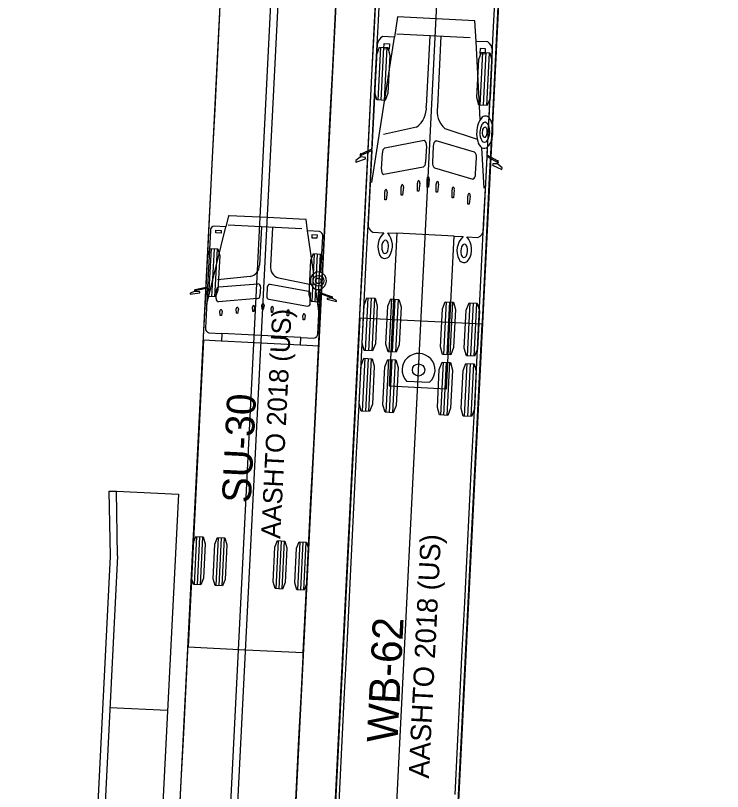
# Model space of a CAD drawing. Extents: x 260275 to 261282, y 610916 to 614143.
# Drawn here: x 261035.2 to 261084.3, y 612189.7 to 612243.5 of the extents above; entities that cross this region are included whole.
import ezdxf

# ---------------------------------------------------------------- set-up
doc = ezdxf.new("R2010")
doc.units = 0
for name, color, linetype in [('GE_X_Alignment', 7, 'Continuous'), ('PV_P_Curb', 7, 'Continuous'), ('PV_P_EOP', 7, 'Continuous'), ('PV_P_Joint', 7, 'Continuous'), ('TopoDOT_Transients', 7, 'Continuous')]:
    doc.layers.add(name, color=color, linetype=linetype)

msp = doc.modelspace()

# ---------------------------------------------------------------- linework, layer by layer
at = {"layer": 'GE_X_Alignment'}
msp.add_line((260986.249, 610915.954), (261148.276, 614142.838), dxfattribs=at)
at = {"layer": 'PV_P_Curb'}
for p, q in [((261041.738, 612210.53), (261042.238, 612210.54)), ((261041.822, 612206.045), (261041.738, 612210.53)), ((261041.82, 612206.041), (261037.345, 612116.921))]:
    msp.add_line(p, q, dxfattribs=at)
at = {"layer": 'PV_P_EOP'}
for p, q in [((261042.238, 612210.54), (261046.541, 612210.324)), ((261042.321, 612206.054), (261042.238, 612210.54)), ((261046.541, 612210.324), (261045.432, 612188.236)), ((261042.321, 612206.054), (261037.849, 612116.977))]:
    msp.add_line(p, q, dxfattribs=at)
at = {"layer": 'PV_P_Joint'}
msp.add_line((261041.794, 612195.543), (261045.789, 612195.343), dxfattribs=at)
at = {"layer": 'TopoDOT_Transients'}
for p, q in [((261059.045, 612136.423), (261081.046, 612574.591)), ((261048.059, 612136.974), (261068.197, 612538.052)), ((261067.093, 612243.166), (261061.729, 612243.435)), ((261066.768, 612241.979), (261061.669, 612242.235)), ((261063.969, 612242.12), (261063.724, 612237.234)), ((261059.937, 612231.949), (261061.508, 612242.018)), ((261064.734, 612242.081), (261064.488, 612237.196)), ((261067.467, 612236.32), (261067.172, 612241.733)), ((261060.537, 612241.326), (261060.353, 612237.663)), ((261060.766, 612241.314), (261060.582, 612237.652)), ((261060.778, 612241.218), (261060.796, 612241.573)), ((261061.156, 612241.199), (261060.778, 612241.218)), ((261060.796, 612241.573), (261061.174, 612241.554)), ((261060.994, 612241.303), (261060.811, 612237.641)), ((261061.174, 612241.554), (261061.156, 612241.199)), ((261067.458, 612241.239), (261067.44, 612240.883)), ((261067.836, 612241.22), (261067.458, 612241.239)), ((261067.818, 612240.864), (261067.836, 612241.22)), ((261068.071, 612236.423), (261068.307, 612241.118)), ((261067.611, 612240.97), (261067.427, 612237.308)), ((261067.44, 612240.883), (261067.818, 612240.864)), ((261067.84, 612240.959), (261067.656, 612237.297)), ((261068.069, 612240.947), (261067.885, 612237.285)), ((261063.051, 612235.787), (261060.759, 612235.268)), ((261065.012, 612235.688), (261067.253, 612234.939)), ((261060.845, 612234.359), (261063.568, 612234.868)), ((261067.064, 612234.047), (261064.406, 612234.826)), ((261063.731, 612234.489), (261063.674, 612233.36)), ((261064.206, 612234.465), (261064.149, 612233.336)), ((261067.727, 612231.558), (261067.574, 612234.358)), ((261059.164, 612233.717), (261059.143, 612233.702)), ((261059.19, 612233.715), (261059.164, 612233.717)), ((261060.618, 612232.868), (261060.675, 612233.997)), ((261067.141, 612232.54), (261067.197, 612233.669)), ((261063.504, 612232.997), (261060.781, 612232.489)), ((261068.646, 612233.24), (261068.672, 612233.24)), ((261068.672, 612233.24), (261068.692, 612233.222)), ((261064.282, 612232.958), (261066.941, 612232.179)), ((261063.784, 612231.619), (261063.775, 612232.17)), ((261063.929, 612232.162), (261063.866, 612231.615)), ((261061.988, 612231.065), (261061.98, 612231.641)), ((261062.134, 612231.634), (261062.07, 612231.061)), ((261063.121, 612231.343), (261063.112, 612231.894)), ((261063.267, 612231.886), (261063.203, 612231.339)), ((261063.866, 612231.615), (261063.784, 612231.619)), ((261064.416, 612231.278), (261064.407, 612231.829)), ((261064.561, 612231.821), (261064.498, 612231.274)), ((261065.515, 612230.888), (261065.506, 612231.439)), ((261065.66, 612231.431), (261065.597, 612230.884)), ((261060.853, 612230.736), (261060.845, 612231.287)), ((261060.999, 612231.279), (261060.935, 612230.732)), ((261062.07, 612231.061), (261061.988, 612231.065)), ((261063.203, 612231.339), (261063.121, 612231.343)), ((261064.498, 612231.274), (261064.416, 612231.278)), ((261065.597, 612230.884), (261065.515, 612230.888)), ((261066.611, 612230.447), (261066.603, 612230.998)), ((261066.757, 612230.99), (261066.693, 612230.443)), ((261060.935, 612230.732), (261060.853, 612230.736)), ((261066.693, 612230.443), (261066.611, 612230.447)), ((261048.494, 612223.403), (261049.834, 612228.871)), ((261055.089, 612228.73), (261049.99, 612228.986)), ((261052.29, 612228.871), (261052.156, 612226.206)), ((261053.054, 612228.832), (261052.921, 612226.167)), ((261049.123, 612228.45), (261049.133, 612228.644)), ((261049.501, 612228.431), (261049.123, 612228.45)), ((261049.133, 612228.644), (261049.511, 612228.625)), ((261049.511, 612228.625), (261049.501, 612228.431)), ((261055.916, 612225.621), (261055.498, 612228.586)), ((261055.795, 612228.31), (261055.785, 612228.116)), ((261056.173, 612228.291), (261055.795, 612228.31)), ((261056.163, 612228.097), (261056.173, 612228.291)), ((261056.419, 612225.711), (261056.546, 612228.23)), ((261060.014, 612228.502), (261060.788, 612228.463)), ((261065.644, 612228.22), (261061.675, 612228.419)), ((261066.53, 612228.175), (261067.305, 612228.136)), ((261055.785, 612228.116), (261056.163, 612228.097)), ((261048.801, 612227.366), (261048.634, 612224.036)), ((261049.009, 612227.355), (261048.842, 612224.026)), ((261049.217, 612227.345), (261049.05, 612224.015)), ((261055.959, 612227.006), (261055.791, 612223.677)), ((261056.167, 612226.996), (261056, 612223.667)), ((261056.375, 612226.985), (261056.208, 612223.656)), ((261051.518, 612225.43), (261049.239, 612225.199)), ((261049.346, 612224.7), (261052.054, 612224.916)), ((261053.478, 612225.331), (261055.734, 612224.871)), ((261049.153, 612223.89), (261049.184, 612224.506)), ((261052.226, 612224.705), (261052.195, 612224.089)), ((261052.701, 612224.681), (261052.67, 612224.065)), ((261055.566, 612224.387), (261052.892, 612224.874)), ((261056.284, 612223.012), (261056.067, 612224.546)), ((261052.033, 612223.895), (261049.325, 612223.679)), ((261052.811, 612223.856), (261055.484, 612223.369)), ((261055.676, 612223.562), (261055.707, 612224.178)), ((261059.664, 612223.947), (261059.48, 612220.285)), ((261059.893, 612223.936), (261059.709, 612220.274)), ((261060.122, 612223.924), (261059.938, 612220.262)), ((261061.312, 612223.865), (261061.128, 612220.203)), ((261061.541, 612223.853), (261061.357, 612220.191)), ((261061.77, 612223.842), (261061.586, 612220.18)), ((261051.688, 612222.999), (261051.667, 612223.301)), ((261051.821, 612223.293), (261051.77, 612222.995)), ((261052.344, 612223.135), (261052.323, 612223.436)), ((261052.477, 612223.428), (261052.426, 612223.131)), ((261065.091, 612223.675), (261064.907, 612220.013)), ((261065.319, 612223.663), (261065.136, 612220.001)), ((261065.548, 612223.652), (261065.364, 612219.99)), ((261066.739, 612223.592), (261066.555, 612219.93)), ((261066.967, 612223.581), (261066.784, 612219.919)), ((261067.196, 612223.569), (261067.012, 612219.907)), ((261049.437, 612222.719), (261049.416, 612223.02)), ((261049.57, 612223.013), (261049.519, 612222.715)), ((261050.563, 612222.873), (261050.542, 612223.188)), ((261050.645, 612222.869), (261050.563, 612222.873)), ((261050.696, 612223.181), (261050.645, 612222.869)), ((261051.77, 612222.995), (261051.688, 612222.999)), ((261052.426, 612223.131), (261052.344, 612223.135)), ((261052.983, 612222.934), (261052.962, 612223.236)), ((261053.065, 612222.93), (261052.983, 612222.934)), ((261053.116, 612223.228), (261053.065, 612222.93)), ((261054.089, 612222.696), (261054.068, 612222.997)), ((261054.223, 612222.99), (261054.172, 612222.692)), ((261049.519, 612222.715), (261049.437, 612222.719)), ((261054.172, 612222.692), (261054.089, 612222.696)), ((261055.195, 612222.43), (261055.174, 612222.731)), ((261055.277, 612222.426), (261055.195, 612222.43)), ((261055.328, 612222.724), (261055.277, 612222.426)), ((261055.037, 612221.196), (261049.552, 612221.472)), ((261055.01, 612220.666), (261049.525, 612220.941)), ((261059.453, 612219.753), (261059.27, 612216.091)), ((261059.682, 612219.741), (261059.498, 612216.079)), ((261059.911, 612219.73), (261059.727, 612216.068)), ((261061.101, 612219.67), (261060.918, 612216.008)), ((261061.33, 612219.658), (261061.146, 612215.996)), ((261061.559, 612219.647), (261061.375, 612215.985)), ((261064.88, 612219.48), (261064.696, 612215.818)), ((261065.109, 612219.469), (261064.925, 612215.807)), ((261065.338, 612219.457), (261065.154, 612215.795)), ((261066.528, 612219.398), (261066.344, 612215.735)), ((261066.757, 612219.386), (261066.573, 612215.724)), ((261066.986, 612219.375), (261066.802, 612215.712)), ((261062.341, 612218.176), (261063.955, 612218.095)), ((261047.798, 612207.391), (261047.631, 612204.062)), ((261048.006, 612207.38), (261047.839, 612204.051)), ((261048.214, 612207.37), (261048.047, 612204.041)), ((261049.296, 612207.315), (261049.129, 612203.986)), ((261049.504, 612207.305), (261049.337, 612203.976)), ((261049.712, 612207.295), (261049.545, 612203.965)), ((261053.458, 612207.106), (261053.29, 612203.777)), ((261053.666, 612207.096), (261053.498, 612203.767)), ((261053.874, 612207.086), (261053.707, 612203.756)), ((261054.956, 612207.031), (261054.789, 612203.702)), ((261055.164, 612207.021), (261054.997, 612203.692)), ((261055.372, 612207.01), (261055.205, 612203.681))]:
    msp.add_line(p, q, dxfattribs=at)
for points in [[(261051.548, 612071.863), (261074.206, 612523.277)], [(261082.631, 612521.243), (261060.03, 612071.291)], [(261042.767, 612111.356), (261063.016, 612514.614)], [(261070.923, 612512.551), (261050.75, 612110.806), (261042.76, 612111.207), (261042.767, 612111.356), (261042.767, 612111.356)], [(261054.56, 612186.696), (261054.728, 612190.025), (261054.895, 612193.353), (261055.062, 612196.681), (261055.229, 612200.01), (261055.396, 612203.338), (261055.563, 612206.667), (261055.73, 612209.995), (261055.897, 612213.324), (261056.065, 612216.652), (261056.232, 612219.981), (261056.399, 612223.309), (261056.566, 612226.637), (261056.733, 612229.966), (261056.9, 612233.294), (261057.067, 612236.623), (261057.234, 612239.951), (261057.402, 612243.28), (261057.569, 612246.608)], [(261054.561, 612186.7), (261054.728, 612190.029), (261054.895, 612193.357), (261055.062, 612196.686), (261055.229, 612200.014), (261055.396, 612203.342), (261055.563, 612206.671), (261055.73, 612209.999), (261055.898, 612213.328), (261056.065, 612216.656), (261056.232, 612219.985), (261056.399, 612223.313), (261056.566, 612226.642), (261056.733, 612229.97), (261056.9, 612233.298), (261057.068, 612236.627), (261057.235, 612239.955), (261057.402, 612243.284), (261057.569, 612246.612)], [(261057.558, 612186.566), (261057.725, 612189.896), (261057.892, 612193.225), (261058.059, 612196.555), (261058.226, 612199.884), (261058.394, 612203.214), (261058.561, 612206.544), (261058.728, 612209.873), (261058.895, 612213.203), (261059.062, 612216.532), (261059.229, 612219.862), (261059.397, 612223.191), (261059.564, 612226.521), (261059.731, 612229.85), (261059.898, 612233.18), (261060.065, 612236.509), (261060.233, 612239.839), (261060.4, 612243.169), (261060.567, 612246.498)], [(261057.45, 612189.416), (261057.618, 612192.746), (261057.785, 612196.075), (261057.952, 612199.405), (261058.119, 612202.734), (261058.286, 612206.064), (261058.454, 612209.394), (261058.621, 612212.723), (261058.788, 612216.053), (261058.955, 612219.382), (261059.122, 612222.712), (261059.289, 612226.041), (261059.457, 612229.371), (261059.624, 612232.7), (261059.791, 612236.03), (261059.958, 612239.359), (261060.125, 612242.689), (261060.293, 612246.019)], [(261065.715, 612189.495), (261065.882, 612192.824), (261066.049, 612196.154), (261066.216, 612199.483), (261066.384, 612202.813), (261066.551, 612206.142), (261066.718, 612209.472), (261066.885, 612212.801), (261067.052, 612216.131), (261067.219, 612219.461), (261067.387, 612222.79), (261067.554, 612226.12), (261067.721, 612229.449), (261067.888, 612232.779), (261068.055, 612236.108), (261068.223, 612239.438), (261068.39, 612242.767), (261068.557, 612246.097)], [(261065.94, 612188.99), (261066.107, 612192.32), (261066.274, 612195.649), (261066.441, 612198.979), (261066.608, 612202.308), (261066.776, 612205.638), (261066.943, 612208.967), (261067.11, 612212.297), (261067.277, 612215.626), (261067.444, 612218.956), (261067.612, 612222.285), (261067.779, 612225.615), (261067.946, 612228.945), (261068.113, 612232.274), (261068.28, 612235.604), (261068.447, 612238.933), (261068.615, 612242.263), (261068.782, 612245.592)], [(261046.57, 612187.097), (261046.738, 612190.426), (261046.905, 612193.754), (261047.072, 612197.083), (261047.239, 612200.411), (261047.406, 612203.739), (261047.573, 612207.068), (261047.74, 612210.396), (261047.907, 612213.725), (261048.075, 612217.053), (261048.242, 612220.382), (261048.409, 612223.71), (261048.576, 612227.039), (261048.743, 612230.367), (261048.91, 612233.695), (261049.077, 612237.024), (261049.244, 612240.352), (261049.412, 612243.681)], [(261046.571, 612187.101), (261046.738, 612190.43), (261046.905, 612193.758), (261047.072, 612197.087), (261047.239, 612200.415), (261047.406, 612203.744), (261047.573, 612207.072), (261047.741, 612210.401), (261047.908, 612213.729), (261048.075, 612217.057), (261048.242, 612220.386), (261048.409, 612223.714), (261048.576, 612227.043), (261048.743, 612230.371), (261048.91, 612233.7), (261049.078, 612237.028), (261049.245, 612240.357), (261049.412, 612243.685)], [(261067.093, 612243.166), (261061.729, 612243.435), (261061.508, 612242.018), (261060.694, 612242.059)], [(261067.985, 612241.693), (261067.172, 612241.733), (261067.094, 612243.154)], [(261060.317, 612241.519), (261059.952, 612234.252), (261059.196, 612233.92)], [(261059.208, 612233.833), (261059.208, 612233.833), (261059.947, 612234.152), (261059.692, 612229.077)], [(261068.661, 612233.445), (261067.942, 612233.85), (261067.971, 612234.423)], [(261059.148, 612233.789), (261059.143, 612233.702), (261058.836, 612233.476), (261058.83, 612233.356), (261059.504, 612233.58), (261059.509, 612233.683), (261059.19, 612233.715), (261059.195, 612233.797)], [(261067.682, 612228.676), (261067.937, 612233.751), (261068.64, 612233.359), (261068.64, 612233.359)], [(261068.65, 612233.322), (261068.646, 612233.24), (261068.326, 612233.24), (261068.32, 612233.137), (261068.968, 612232.847), (261068.974, 612232.967), (261068.692, 612233.222), (261068.695, 612233.31)], [(261056.308, 612228.546), (261055.501, 612228.586), (261055.497, 612228.591), (261055.387, 612229.369), (261055.345, 612229.373), (261052.705, 612229.506), (261050.065, 612229.638), (261050.022, 612229.638), (261049.835, 612228.875), (261049.83, 612228.871), (261049.024, 612228.911)], [(261048.756, 612228.621), (261048.558, 612224.693), (261048.551, 612224.682), (261047.709, 612224.497), (261047.708, 612224.498)], [(261061.045, 612228.451), (261061.675, 612228.419), (261061.143, 612217.832), (261065.112, 612217.633), (261065.644, 612228.22), (261066.273, 612228.188)], [(261047.664, 612224.427), (261047.661, 612224.38), (261047.661, 612224.379), (261047.36, 612224.262), (261047.356, 612224.198), (261047.359, 612224.198), (261048.021, 612224.304), (261048.024, 612224.305), (261048.027, 612224.36), (261048.025, 612224.361), (261047.708, 612224.385), (261047.708, 612224.386), (261047.711, 612224.43)], [(261047.723, 612224.449), (261047.723, 612224.449), (261048.55, 612224.628), (261048.554, 612224.615), (261048.415, 612221.845)], [(261057.175, 612224.022), (261057.174, 612224.022), (261056.355, 612224.29), (261056.349, 612224.302), (261056.36, 612224.53)], [(261056.206, 612221.454), (261056.345, 612224.224), (261056.35, 612224.236), (261057.155, 612223.976), (261057.155, 612223.976)], [(261057.166, 612223.955), (261057.164, 612223.911), (261057.164, 612223.91), (261056.846, 612223.918), (261056.844, 612223.918), (261056.841, 612223.862), (261056.844, 612223.861), (261057.492, 612223.689), (261057.495, 612223.688), (261057.498, 612223.753), (261057.21, 612223.9), (261057.21, 612223.9), (261057.212, 612223.947)], [(261065.177, 612174.246), (261065.199, 612174.245), (261067.603, 612222.114), (261063.358, 612222.327), (261059.114, 612222.54), (261056.71, 612174.671), (261056.732, 612174.67)], [(261048.654, 612221.517), (261049.549, 612221.472), (261049.552, 612221.468), (261049.525, 612220.942), (261049.514, 612220.942), (261048.273, 612221.004), (261047.205, 612199.744), (261051.2, 612199.543), (261055.195, 612199.343), (261056.263, 612220.603), (261055.021, 612220.665), (261055.01, 612220.666), (261055.037, 612221.193), (261055.04, 612221.196), (261055.935, 612221.151)]]:
    msp.add_lwpolyline(points, dxfattribs=at)
for points in [[(261060.48, 612241.328), (261061.051, 612241.3), (261061.198, 612240.778), (261061.065, 612238.142), (261060.867, 612237.638), (261060.296, 612237.666), (261060.15, 612238.188), (261060.282, 612240.824)], [(261067.554, 612240.973), (261068.126, 612240.944), (261068.272, 612240.423), (261068.14, 612237.786), (261067.942, 612237.282), (261067.37, 612237.311), (261067.224, 612237.832), (261067.356, 612240.469)], [(261048.749, 612227.368), (261049.269, 612227.342), (261049.402, 612226.868), (261049.281, 612224.471), (261049.102, 612224.013), (261048.582, 612224.039), (261048.449, 612224.513), (261048.57, 612226.91)], [(261055.907, 612227.009), (261056.426, 612226.983), (261056.559, 612226.509), (261056.439, 612224.112), (261056.259, 612223.653), (261055.74, 612223.68), (261055.607, 612224.153), (261055.727, 612226.55)], [(261059.607, 612223.95), (261060.179, 612223.922), (261060.325, 612223.4), (261060.193, 612220.764), (261059.995, 612220.26), (261059.423, 612220.288), (261059.277, 612220.81), (261059.409, 612223.446)], [(261061.255, 612223.868), (261061.827, 612223.839), (261061.973, 612223.318), (261061.841, 612220.681), (261061.643, 612220.177), (261061.071, 612220.205), (261060.925, 612220.727), (261061.057, 612223.363)], [(261065.034, 612223.678), (261065.605, 612223.649), (261065.751, 612223.128), (261065.619, 612220.491), (261065.421, 612219.987), (261064.85, 612220.016), (261064.704, 612220.537), (261064.836, 612223.174)], [(261066.682, 612223.595), (261067.253, 612223.566), (261067.399, 612223.045), (261067.267, 612220.408), (261067.069, 612219.904), (261066.498, 612219.933), (261066.351, 612220.454), (261066.484, 612223.091)], [(261059.397, 612219.756), (261059.968, 612219.727), (261060.114, 612219.206), (261059.982, 612216.569), (261059.784, 612216.065), (261059.213, 612216.094), (261059.066, 612216.615), (261059.199, 612219.252)], [(261061.045, 612219.673), (261061.616, 612219.644), (261061.762, 612219.123), (261061.63, 612216.486), (261061.432, 612215.982), (261060.861, 612216.011), (261060.714, 612216.532), (261060.847, 612219.169)], [(261064.823, 612219.483), (261065.394, 612219.454), (261065.541, 612218.933), (261065.408, 612216.296), (261065.211, 612215.792), (261064.639, 612215.821), (261064.493, 612216.342), (261064.625, 612218.979)], [(261066.471, 612219.4), (261067.042, 612219.372), (261067.189, 612218.85), (261067.056, 612216.214), (261066.859, 612215.71), (261066.287, 612215.738), (261066.141, 612216.26), (261066.273, 612218.896)], [(261047.746, 612207.393), (261048.266, 612207.367), (261048.399, 612206.893), (261048.278, 612204.496), (261048.099, 612204.038), (261047.579, 612204.064), (261047.446, 612204.538), (261047.567, 612206.935)], [(261049.245, 612207.318), (261049.764, 612207.292), (261049.897, 612206.818), (261049.777, 612204.421), (261049.597, 612203.963), (261049.077, 612203.989), (261048.944, 612204.463), (261049.065, 612206.86)], [(261053.406, 612207.109), (261053.925, 612207.083), (261054.058, 612206.609), (261053.938, 612204.212), (261053.758, 612203.754), (261053.239, 612203.78), (261053.106, 612204.254), (261053.226, 612206.651)], [(261054.904, 612207.034), (261055.423, 612207.008), (261055.556, 612206.534), (261055.436, 612204.137), (261055.256, 612203.679), (261054.737, 612203.705), (261054.604, 612204.179), (261054.724, 612206.576)]]:
    msp.add_lwpolyline(points, close=True, dxfattribs=at)
for centre, radius in [((261056.245, 612225.128), 0.374), ((261056.245, 612225.128), 0.193), ((261063.188, 612218.943), 0.424)]:
    msp.add_circle(centre, radius, dxfattribs=at)
for centre, radius, start, end in [((261061.095, 612241.376), 0.792, 120.4366, 169.5921), ((261067.518, 612241.054), 0.792, 4.6589, 53.8144), ((261062.097, 612237.11), 1.631, 305.8013, 4.3921), ((261066.094, 612236.909), 1.631, 169.8589, 228.4497), ((261068.345, 612235.701), 1.074, 138.5821, 162.851), ((261067.835, 612236.172), 0.38, 90.4559, 140.9794), ((261067.81, 612236.225), 0.328, 37.2138, 86.1182), ((261067.553, 612235.925), 0.719, 15.6559, 43.9129), ((261069.263, 612235.368), 2.049, 161.5065, 177.4318), ((261068.531, 612235.416), 1.098, 150.3913, 178.2839), ((261067.821, 612235.849), 0.268, 92.1981, 155.8758), ((261067.878, 612235.529), 0.27, 108.2744, 181.0182), ((261067.718, 612235.578), 0.22, 8.1354, 69.8336), ((261067.679, 612235.731), 0.407, 8.3561, 71.1606), ((261066.886, 612235.484), 1.234, 356.7552, 14.3373), ((261066.606, 612235.564), 1.731, 3.5106, 18.7084), ((261066.135, 612235.517), 2.204, 344.3246, 3.9597), ((261069.224, 612235.346), 2.012, 176.7669, 195.4498), ((261068.343, 612235.353), 0.914, 173.9599, 216.0179), ((261068.215, 612235.41), 0.617, 169.4131, 202.6039), ((261067.763, 612235.199), 0.12, 192.1016, 337.5796), ((261067.322, 612235.459), 0.631, 330.9338, 13.7343), ((261067.205, 612235.403), 0.913, 320.4351, 0.6954), ((261063.397, 612234.575), 0.342, 348.7273, 58.6538), ((261064.547, 612234.518), 0.342, 115.5972, 185.5237), ((261068.064, 612234.989), 0.799, 192.9249, 232.1926), ((261067.753, 612234.945), 0.199, 220.9288, 321.5681), ((261067.352, 612235.109), 0.924, 312.0226, 348.3008), ((261061.077, 612234.029), 0.403, 125.1252, 184.5832), ((261067.736, 612234.611), 0.301, 237.3568, 321.2551), ((261059.259, 612233.851), 0.127, 145.0209, 209.2301), ((261059.174, 612233.909), 0.0244, 27.9931, 141.3075), ((261059.099, 612233.852), 0.11, 330.073, 350.1813), ((261066.8, 612233.742), 0.403, 349.6678, 49.1258), ((261063.277, 612233.323), 0.397, 304.8867, 3.0497), ((261064.541, 612233.26), 0.397, 171.2013, 229.3643), ((261068.75, 612233.367), 0.11, 184.0697, 204.178), ((261068.682, 612233.431), 0.0244, 32.9435, 146.2579), ((261068.591, 612233.382), 0.127, 325.0209, 29.2301), ((261060.943, 612232.78), 0.334, 168.2627, 240.8606), ((261066.808, 612232.486), 0.334, 293.3904, 5.9883), ((261063.302, 612231.926), 0.192, 122.2012, 189.6758), ((261063.081, 612231.937), 0.192, 344.5479, 52.0772), ((261063.965, 612232.202), 0.192, 122.2012, 189.6758), ((261063.744, 612232.213), 0.192, 344.5752, 52.0498), ((261064.597, 612231.861), 0.192, 122.1738, 189.7031), ((261064.376, 612231.872), 0.192, 344.5752, 52.0498), ((261061.034, 612231.319), 0.192, 122.2012, 189.6758), ((261060.814, 612231.33), 0.192, 344.5479, 52.0772), ((261062.169, 612231.649), 0.192, 122.2012, 189.6758), ((261061.949, 612231.66), 0.192, 344.5479, 52.0772), ((261065.696, 612231.472), 0.192, 122.1738, 189.7031), ((261065.475, 612231.483), 0.192, 344.5752, 52.0498), ((261066.792, 612231.03), 0.192, 122.1738, 189.7031), ((261066.572, 612231.041), 0.192, 344.5752, 52.0498), ((261049.037, 612228.63), 0.282, 92.6739, 181.7533), ((261060.26, 612229.018), 0.571, 174.0409, 244.4325), ((261067.111, 612228.674), 0.571, 289.8185, 0.2101), ((261056.267, 612228.267), 0.282, 352.4977, 81.5771), ((261061.707, 612227.483), 1.344, 133.1609, 206.7157), ((261060.033, 612227.567), 1.344, 327.5353, 41.0901), ((261067.192, 612227.208), 1.344, 133.1609, 206.7157), ((261065.518, 612227.292), 1.344, 327.5353, 41.0901), ((261061.492, 612227.454), 0.86, 158.6915, 198.6609), ((261060.965, 612227.672), 0.29, 104.7698, 160.9298), ((261060.829, 612227.713), 0.247, 5.5291, 75.4082), ((261060.224, 612227.516), 0.879, 339.9934, 14.5886), ((261066.414, 612227.433), 0.247, 98.8428, 168.7219), ((261066.275, 612227.405), 0.29, 13.3212, 69.4812), ((261060.898, 612227.236), 0.228, 194.4278, 256.3226), ((261060.795, 612227.272), 0.262, 280.9175, 347.4427), ((261066.996, 612227.176), 0.879, 159.6624, 194.2576), ((261065.729, 612227.242), 0.86, 335.5901, 15.5595), ((261060.847, 612227.065), 0.387, 208.621, 325.63), ((261066.331, 612226.781), 0.383, 207.5963, 326.6547), ((261066.404, 612226.99), 0.262, 186.8083, 253.3335), ((261066.298, 612226.965), 0.228, 277.9284, 339.8232), ((261051.383, 612226.191), 0.773, 280.016, 1.1001), ((261053.688, 612226.075), 0.773, 173.1509, 254.235), ((261056.313, 612225.133), 0.629, 129.1711, 177.8604), ((261056.249, 612225.214), 0.526, 71.0707, 129.3167), ((261056.178, 612225.131), 0.628, 286.8788, 67.3705), ((261052.043, 612224.732), 0.184, 351.6672, 86.5274), ((261056.313, 612225.117), 0.63, 176.4803, 228.8831), ((261047.687, 612224.462), 0.0418, 59.6174, 236.6324), ((261047.681, 612224.462), 0.0434, 312.5392, 343.212), ((261049.377, 612224.51), 0.193, 99.2679, 181.1824), ((261052.885, 612224.689), 0.184, 87.7236, 182.5838), ((261055.516, 612224.201), 0.193, 353.0686, 74.9831), ((261056.24, 612225.041), 0.524, 229.3845, 283.1846), ((261049.336, 612223.863), 0.184, 171.6617, 266.5329), ((261052.002, 612224.085), 0.193, 279.263, 1.1873), ((261052.861, 612224.042), 0.193, 173.0637, 254.988), ((261057.198, 612223.984), 0.0434, 191.039, 221.7118), ((261057.192, 612223.984), 0.0418, 297.6187, 114.6336), ((261051.757, 612223.315), 0.091, 94.6451, 188.8089), ((261051.733, 612223.316), 0.0909, 345.4064, 79.6416), ((261052.413, 612223.45), 0.091, 94.6451, 188.8089), ((261052.389, 612223.451), 0.091, 345.4421, 79.6059), ((261053.052, 612223.25), 0.0909, 94.6094, 188.8446), ((261053.028, 612223.251), 0.091, 345.4421, 79.6059), ((261055.492, 612223.554), 0.184, 267.7181, 2.5893), ((261049.506, 612223.034), 0.091, 94.6451, 188.8089), ((261049.482, 612223.036), 0.0909, 345.4064, 79.6416), ((261050.632, 612223.188), 0.091, 94.6451, 188.8089), ((261050.608, 612223.19), 0.0909, 345.4064, 79.6416), ((261054.158, 612223.011), 0.0909, 94.6094, 188.8446), ((261054.135, 612223.013), 0.091, 345.4421, 79.6059), ((261055.264, 612222.745), 0.0909, 94.6094, 188.8446), ((261055.24, 612222.746), 0.091, 345.4421, 79.6059), ((261048.738, 612221.829), 0.323, 177.1255, 254.9739), ((261055.883, 612221.47), 0.323, 279.2771, 357.1255), ((261063.188, 612218.943), 1.143, 312.1255, 222.1255)]:
    msp.add_arc(centre, radius, start, end, dxfattribs=at)
for centre, major_axis, start_param, end_param in [((261059.171, 612233.855), (-0.0039, -0.0781), 5.756759, 7.026061), ((261059.171, 612233.855), (0.0039, 0.0781), 4.442794, 5.713538), ((261068.679, 612233.378), (-0.0039, -0.0781), 3.71124, 4.981984), ((261068.679, 612233.378), (0.0039, 0.0781), 2.398717, 3.668019)]:
    msp.add_ellipse(centre, major_axis=major_axis, ratio=0.5, start_param=start_param, end_param=end_param, dxfattribs=at)

# ---------------------------------------------------------------- texts
for s, height, p in [('AASHTO 2018 (US)', 1.33333, (261053.595, 612207.219)), ('SU-30', 2, (261051.549, 612209.682)), ('AASHTO 2018 (US)', 1.41667, (261063.9, 612190.595)), ('WB-62', 2.125, (261061.719, 612193.06))]:
    msp.add_text(s, height=height, rotation=87.1255, dxfattribs=at).set_placement(p)

doc.saveas('drawing.dxf')
